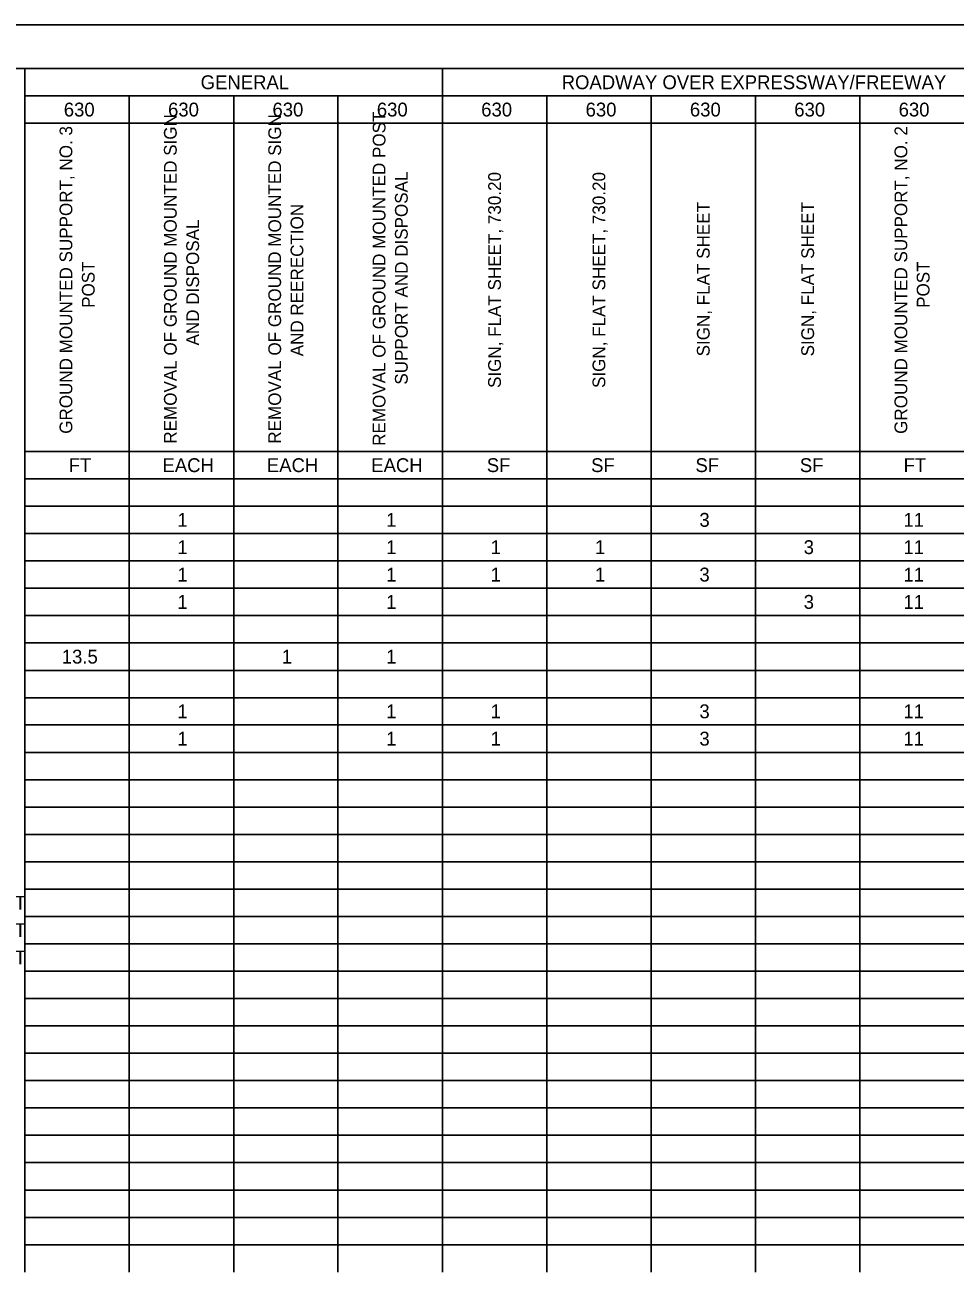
# Model space of a CAD drawing. Extents: x 0 to 34, y 0 to 22.
# Drawn here: x 12.87 to 23.52, y 7.71 to 22 of the extents above; entities that cross this region are included whole.
import ezdxf

# ---------------------------------------------------------------- set-up
doc = ezdxf.new("R2010")
doc.units = 0
for name, color, linetype in [('SH_Border', 7, 'Continuous'), ('SH_Cut_Line', 7, 'Continuous'), ('SH_Text', 7, 'Continuous')]:
    doc.layers.add(name, color=color, linetype=linetype)

msp = doc.modelspace()

# ---------------------------------------------------------------- linework, layer by layer
at = {"layer": 'SH_Border'}
msp.add_lwpolyline([(1.5, 21.5), (33.5, 21.5), (33.5, 0.5), (1.5, 0.5)], close=True, dxfattribs=at)
at = {"layer": 'SH_Cut_Line'}
msp.add_lwpolyline([(0, 0), (34, 0), (34, 22), (0, 22)], close=True, dxfattribs=at)
at = {"layer": 'SH_Text'}
for p, q in [((12.867, 21.5), (14.063, 21.5)), ((12.867, 21.5), (12.867, 21.187)), ((14.063, 21.5), (16.454, 21.5)), ((16.454, 21.5), (23.629, 21.5)), ((17.65, 21.5), (17.65, 21.187)), ((12.867, 21.187), (14.063, 21.187)), ((12.867, 21.187), (12.867, 20.873)), ((14.063, 21.187), (16.454, 21.187)), ((14.063, 21.187), (14.063, 20.873)), ((15.259, 21.187), (15.259, 20.873)), ((16.454, 21.187), (23.629, 21.187)), ((16.454, 21.187), (16.454, 20.873)), ((17.65, 21.187), (17.65, 20.873)), ((18.846, 21.187), (18.846, 20.873)), ((20.042, 21.187), (20.042, 20.873)), ((21.238, 21.187), (21.238, 20.873)), ((22.434, 21.187), (22.434, 20.873)), ((12.867, 20.873), (14.063, 20.873)), ((12.867, 20.873), (12.867, 20.56)), ((14.063, 20.873), (16.454, 20.873)), ((14.063, 20.873), (14.063, 20.56)), ((15.259, 20.873), (15.259, 20.56)), ((16.454, 20.873), (23.629, 20.873)), ((16.454, 20.873), (16.454, 20.56)), ((17.65, 20.873), (17.65, 20.56)), ((18.846, 20.873), (18.846, 20.56)), ((20.042, 20.873), (20.042, 20.56)), ((21.238, 20.873), (21.238, 20.56)), ((22.434, 20.873), (22.434, 20.56)), ((12.867, 20.56), (12.867, 19.933)), ((14.063, 20.56), (14.063, 19.933)), ((15.259, 20.56), (15.259, 19.933)), ((16.454, 20.56), (16.454, 19.933)), ((17.65, 20.56), (17.65, 19.933)), ((18.846, 20.56), (18.846, 19.933)), ((20.042, 20.56), (20.042, 19.933)), ((21.238, 20.56), (21.238, 19.933)), ((22.434, 20.56), (22.434, 19.933)), ((12.867, 19.933), (12.867, 19.619)), ((14.063, 19.933), (14.063, 19.619)), ((15.259, 19.933), (15.259, 19.619)), ((16.454, 19.933), (16.454, 19.619)), ((17.65, 19.933), (17.65, 19.619)), ((18.846, 19.933), (18.846, 19.619)), ((20.042, 19.933), (20.042, 19.619)), ((21.238, 19.933), (21.238, 19.619)), ((22.434, 19.933), (22.434, 19.619)), ((12.867, 19.619), (12.867, 19.306)), ((14.063, 19.619), (14.063, 19.306)), ((15.259, 19.619), (15.259, 19.306)), ((16.454, 19.619), (16.454, 19.306)), ((17.65, 19.619), (17.65, 19.306)), ((18.846, 19.619), (18.846, 19.306)), ((20.042, 19.619), (20.042, 19.306)), ((21.238, 19.619), (21.238, 19.306)), ((22.434, 19.619), (22.434, 19.306)), ((12.867, 19.306), (12.867, 18.993)), ((14.063, 19.306), (14.063, 18.993)), ((15.259, 19.306), (15.259, 18.993)), ((16.454, 19.306), (16.454, 18.993)), ((17.65, 19.306), (17.65, 18.993)), ((18.846, 19.306), (18.846, 18.993)), ((20.042, 19.306), (20.042, 18.993)), ((21.238, 19.306), (21.238, 18.993)), ((22.434, 19.306), (22.434, 18.993)), ((12.867, 18.993), (12.867, 18.679)), ((14.063, 18.993), (14.063, 18.679)), ((15.259, 18.993), (15.259, 18.679)), ((16.454, 18.993), (16.454, 18.679)), ((17.65, 18.993), (17.65, 18.679)), ((18.846, 18.993), (18.846, 18.679)), ((20.042, 18.993), (20.042, 18.679)), ((21.238, 18.993), (21.238, 18.679)), ((22.434, 18.993), (22.434, 18.679)), ((12.867, 18.679), (12.867, 18.366)), ((14.063, 18.679), (14.063, 18.366)), ((15.259, 18.679), (15.259, 18.366)), ((16.454, 18.679), (16.454, 18.366)), ((17.65, 18.679), (17.65, 18.366)), ((18.846, 18.679), (18.846, 18.366)), ((20.042, 18.679), (20.042, 18.366)), ((21.238, 18.679), (21.238, 18.366)), ((22.434, 18.679), (22.434, 18.366)), ((12.867, 18.366), (12.867, 18.052)), ((14.063, 18.366), (14.063, 18.052)), ((15.259, 18.366), (15.259, 18.052)), ((16.454, 18.366), (16.454, 18.052)), ((17.65, 18.366), (17.65, 18.052)), ((18.846, 18.366), (18.846, 18.052)), ((20.042, 18.366), (20.042, 18.052)), ((21.238, 18.366), (21.238, 18.052)), ((22.434, 18.366), (22.434, 18.052)), ((12.867, 18.052), (12.867, 17.739)), ((14.063, 18.052), (14.063, 17.739)), ((15.259, 18.052), (15.259, 17.739)), ((16.454, 18.052), (16.454, 17.739)), ((17.65, 18.052), (17.65, 17.739)), ((18.846, 18.052), (18.846, 17.739)), ((20.042, 18.052), (20.042, 17.739)), ((21.238, 18.052), (21.238, 17.739)), ((22.434, 18.052), (22.434, 17.739)), ((12.867, 17.739), (12.867, 17.425)), ((14.063, 17.739), (14.063, 17.425)), ((15.259, 17.739), (15.259, 17.425)), ((16.454, 17.739), (16.454, 17.425)), ((17.65, 17.739), (17.65, 17.425)), ((18.846, 17.739), (18.846, 17.425)), ((20.042, 17.739), (20.042, 17.425)), ((21.238, 17.739), (21.238, 17.425)), ((22.434, 17.739), (22.434, 17.425)), ((12.867, 17.425), (12.867, 16.799)), ((14.063, 17.425), (14.063, 16.799)), ((15.259, 17.425), (15.259, 16.799)), ((16.454, 17.425), (16.454, 16.799)), ((17.65, 17.425), (17.65, 16.799)), ((18.846, 17.425), (18.846, 16.799)), ((20.042, 17.425), (20.042, 16.799)), ((21.238, 17.425), (21.238, 16.799)), ((22.434, 17.425), (22.434, 16.799)), ((12.867, 17.112), (14.063, 17.112)), ((14.063, 17.112), (16.454, 17.112)), ((16.454, 17.112), (23.629, 17.112)), ((12.867, 16.799), (14.063, 16.799)), ((12.867, 16.799), (12.867, 16.485)), ((14.063, 16.799), (16.454, 16.799)), ((14.063, 16.799), (14.063, 16.485)), ((15.259, 16.799), (15.259, 16.485)), ((16.454, 16.799), (23.629, 16.799)), ((16.454, 16.799), (16.454, 16.485)), ((17.65, 16.799), (17.65, 16.485)), ((18.846, 16.799), (18.846, 16.485)), ((20.042, 16.799), (20.042, 16.485)), ((21.238, 16.799), (21.238, 16.485)), ((22.434, 16.799), (22.434, 16.485)), ((12.867, 16.485), (14.063, 16.485)), ((12.867, 16.485), (12.867, 15.231)), ((14.063, 16.485), (16.454, 16.485)), ((14.063, 16.485), (14.063, 15.231)), ((15.259, 16.485), (15.259, 15.231)), ((16.454, 16.485), (23.629, 16.485)), ((16.454, 16.485), (16.454, 15.231)), ((17.65, 16.485), (17.65, 15.231)), ((18.846, 16.485), (18.846, 15.231)), ((20.042, 16.485), (20.042, 15.231)), ((21.238, 16.485), (21.238, 15.231)), ((22.434, 16.485), (22.434, 15.231)), ((12.867, 16.172), (14.063, 16.172)), ((14.063, 16.172), (16.454, 16.172)), ((16.454, 16.172), (23.629, 16.172)), ((12.867, 15.858), (14.063, 15.858)), ((14.063, 15.858), (16.454, 15.858)), ((16.454, 15.858), (23.629, 15.858)), ((12.867, 15.545), (14.063, 15.545)), ((14.063, 15.545), (16.454, 15.545)), ((16.454, 15.545), (23.629, 15.545)), ((12.867, 15.231), (14.063, 15.231)), ((12.867, 15.231), (12.867, 14.291)), ((14.063, 15.231), (16.454, 15.231)), ((14.063, 15.231), (14.063, 14.291)), ((15.259, 15.231), (15.259, 14.291)), ((16.454, 15.231), (23.629, 15.231)), ((16.454, 15.231), (16.454, 14.291)), ((17.65, 15.231), (17.65, 14.291)), ((18.846, 15.231), (18.846, 14.291)), ((20.042, 15.231), (20.042, 14.291)), ((21.238, 15.231), (21.238, 14.291)), ((22.434, 15.231), (22.434, 14.291)), ((12.867, 14.918), (14.063, 14.918)), ((14.063, 14.918), (16.454, 14.918)), ((16.454, 14.918), (23.629, 14.918)), ((12.867, 14.604), (14.063, 14.604)), ((14.063, 14.604), (16.454, 14.604)), ((16.454, 14.604), (23.629, 14.604)), ((12.867, 14.291), (14.063, 14.291)), ((12.867, 14.291), (12.867, 13.664)), ((14.063, 14.291), (16.454, 14.291)), ((14.063, 14.291), (14.063, 13.664)), ((15.259, 14.291), (15.259, 13.664)), ((16.454, 14.291), (23.629, 14.291)), ((16.454, 14.291), (16.454, 13.664)), ((17.65, 14.291), (17.65, 13.664)), ((18.846, 14.291), (18.846, 13.664)), ((20.042, 14.291), (20.042, 13.664)), ((21.238, 14.291), (21.238, 13.664)), ((22.434, 14.291), (22.434, 13.664)), ((12.867, 13.978), (14.063, 13.978)), ((14.063, 13.978), (16.454, 13.978)), ((16.454, 13.978), (23.629, 13.978)), ((12.867, 13.664), (14.063, 13.664)), ((12.867, 13.664), (12.867, 13.351)), ((14.063, 13.664), (16.454, 13.664)), ((14.063, 13.664), (14.063, 13.351)), ((15.259, 13.664), (15.259, 13.351)), ((16.454, 13.664), (23.629, 13.664)), ((16.454, 13.664), (16.454, 13.351)), ((17.65, 13.664), (17.65, 13.351)), ((18.846, 13.664), (18.846, 13.351)), ((20.042, 13.664), (20.042, 13.351)), ((21.238, 13.664), (21.238, 13.351)), ((22.434, 13.664), (22.434, 13.351)), ((12.867, 13.351), (14.063, 13.351)), ((12.867, 13.351), (12.867, 13.037)), ((14.063, 13.351), (16.454, 13.351)), ((14.063, 13.351), (14.063, 13.037)), ((15.259, 13.351), (15.259, 13.037)), ((16.454, 13.351), (23.629, 13.351)), ((16.454, 13.351), (16.454, 13.037)), ((17.65, 13.351), (17.65, 13.037)), ((18.846, 13.351), (18.846, 13.037)), ((20.042, 13.351), (20.042, 13.037)), ((21.238, 13.351), (21.238, 13.037)), ((22.434, 13.351), (22.434, 13.037)), ((12.867, 13.037), (14.063, 13.037)), ((12.867, 13.037), (12.867, 12.41)), ((14.063, 13.037), (16.454, 13.037)), ((14.063, 13.037), (14.063, 12.41)), ((15.259, 13.037), (15.259, 12.41)), ((16.454, 13.037), (23.629, 13.037)), ((16.454, 13.037), (16.454, 12.41)), ((17.65, 13.037), (17.65, 12.41)), ((18.846, 13.037), (18.846, 12.41)), ((20.042, 13.037), (20.042, 12.41)), ((21.238, 13.037), (21.238, 12.41)), ((22.434, 13.037), (22.434, 12.41)), ((12.867, 12.724), (14.063, 12.724)), ((14.063, 12.724), (16.454, 12.724)), ((16.454, 12.724), (23.629, 12.724)), ((12.867, 12.41), (14.063, 12.41)), ((12.867, 12.41), (12.867, 11.47)), ((14.063, 12.41), (16.454, 12.41)), ((14.063, 12.41), (14.063, 11.47)), ((15.259, 12.41), (15.259, 11.47)), ((16.454, 12.41), (23.629, 12.41)), ((16.454, 12.41), (16.454, 11.47)), ((17.65, 12.41), (17.65, 11.47)), ((18.846, 12.41), (18.846, 11.47)), ((20.042, 12.41), (20.042, 11.47)), ((21.238, 12.41), (21.238, 11.47)), ((22.434, 12.41), (22.434, 11.47)), ((12.867, 12.097), (14.063, 12.097)), ((14.063, 12.097), (16.454, 12.097)), ((16.454, 12.097), (23.629, 12.097)), ((12.867, 11.784), (14.063, 11.784)), ((14.063, 11.784), (16.454, 11.784)), ((16.454, 11.784), (23.629, 11.784)), ((12.867, 11.47), (14.063, 11.47)), ((12.867, 11.47), (12.867, 10.843)), ((14.063, 11.47), (16.454, 11.47)), ((14.063, 11.47), (14.063, 10.843)), ((15.259, 11.47), (15.259, 10.843)), ((16.454, 11.47), (23.629, 11.47)), ((16.454, 11.47), (16.454, 10.843)), ((17.65, 11.47), (17.65, 10.843)), ((18.846, 11.47), (18.846, 10.843)), ((20.042, 11.47), (20.042, 10.843)), ((21.238, 11.47), (21.238, 10.843)), ((22.434, 11.47), (22.434, 10.843)), ((12.867, 11.157), (14.063, 11.157)), ((14.063, 11.157), (16.454, 11.157)), ((16.454, 11.157), (23.629, 11.157)), ((12.867, 10.843), (14.063, 10.843)), ((12.867, 10.843), (12.867, 9.903)), ((14.063, 10.843), (16.454, 10.843)), ((14.063, 10.843), (14.063, 9.903)), ((15.259, 10.843), (15.259, 9.903)), ((16.454, 10.843), (23.629, 10.843)), ((16.454, 10.843), (16.454, 9.903)), ((17.65, 10.843), (17.65, 9.903)), ((18.846, 10.843), (18.846, 9.903)), ((20.042, 10.843), (20.042, 9.903)), ((21.238, 10.843), (21.238, 9.903)), ((22.434, 10.843), (22.434, 9.903)), ((12.867, 10.53), (14.063, 10.53)), ((14.063, 10.53), (16.454, 10.53)), ((16.454, 10.53), (23.629, 10.53)), ((12.867, 10.216), (14.063, 10.216)), ((14.063, 10.216), (16.454, 10.216)), ((16.454, 10.216), (23.629, 10.216)), ((12.867, 9.903), (14.063, 9.903)), ((12.867, 9.903), (12.867, 9.276)), ((14.063, 9.903), (16.454, 9.903)), ((14.063, 9.903), (14.063, 9.276)), ((15.259, 9.903), (15.259, 9.276)), ((16.454, 9.903), (23.629, 9.903)), ((16.454, 9.903), (16.454, 9.276)), ((17.65, 9.903), (17.65, 9.276)), ((18.846, 9.903), (18.846, 9.276)), ((20.042, 9.903), (20.042, 9.276)), ((21.238, 9.903), (21.238, 9.276)), ((22.434, 9.903), (22.434, 9.276)), ((12.867, 9.59), (14.063, 9.59)), ((14.063, 9.59), (16.454, 9.59)), ((16.454, 9.59), (23.629, 9.59)), ((12.867, 9.276), (14.063, 9.276)), ((12.867, 9.276), (12.867, 8.336)), ((14.063, 9.276), (16.454, 9.276)), ((14.063, 9.276), (14.063, 8.336)), ((15.259, 9.276), (15.259, 8.336)), ((16.454, 9.276), (23.629, 9.276)), ((16.454, 9.276), (16.454, 8.336)), ((17.65, 9.276), (17.65, 8.336)), ((18.846, 9.276), (18.846, 8.336)), ((20.042, 9.276), (20.042, 8.336)), ((21.238, 9.276), (21.238, 8.336)), ((22.434, 9.276), (22.434, 8.336)), ((12.867, 8.963), (14.063, 8.963)), ((14.063, 8.963), (16.454, 8.963)), ((16.454, 8.963), (23.629, 8.963)), ((12.867, 8.649), (14.063, 8.649)), ((14.063, 8.649), (16.454, 8.649)), ((16.454, 8.649), (23.629, 8.649)), ((12.867, 8.336), (14.063, 8.336)), ((12.867, 8.336), (12.867, 7.709)), ((14.063, 8.336), (16.454, 8.336)), ((14.063, 8.336), (14.063, 7.709)), ((15.259, 8.336), (15.259, 7.709)), ((16.454, 8.336), (23.629, 8.336)), ((16.454, 8.336), (16.454, 7.709)), ((17.65, 8.336), (17.65, 7.709)), ((18.846, 8.336), (18.846, 7.709)), ((20.042, 8.336), (20.042, 7.709)), ((21.238, 8.336), (21.238, 7.709)), ((22.434, 8.336), (22.434, 7.709)), ((12.867, 8.022), (14.063, 8.022)), ((14.063, 8.022), (16.454, 8.022)), ((16.454, 8.022), (23.629, 8.022))]:
    msp.add_line(p, q, dxfattribs=at)

# ---------------------------------------------------------------- texts
for s, height, p in [('GENERAL', 0.1586, (14.88, 21.264)), ('ROADWAY OVER EXPRESSWAY/FREEWAY', 0.15858, (19.017, 21.264)), ('630', 0.1586, (13.312, 20.951)), ('630', 0.1586, (14.507, 20.951)), ('630', 0.1586, (15.703, 20.951)), ('630', 0.1586, (16.899, 20.951)), ('630', 0.1586, (18.095, 20.951)), ('630', 0.1586, (19.291, 20.951)), ('630', 0.1586, (20.486, 20.951)), ('630', 0.1586, (21.682, 20.951)), ('630', 0.1586, (22.878, 20.951)), ('FT', 0.1586, (13.368, 16.876)), ('EACH', 0.1586, (14.443, 16.876)), ('EACH', 0.1586, (15.639, 16.876)), ('EACH', 0.1586, (16.835, 16.876)), ('SF', 0.1586, (18.159, 16.876)), ('SF', 0.1586, (19.354, 16.876)), ('SF', 0.1586, (20.55, 16.876)), ('SF', 0.1586, (21.746, 16.876)), ('FT', 0.1586, (22.935, 16.876)), ('1', 0.159, (14.614, 16.249)), ('1', 0.159, (17.006, 16.249)), ('3', 0.159, (20.595, 16.249)), ('11', 0.1586, (22.933, 16.249)), ('1', 0.159, (14.614, 15.936)), ('1', 0.159, (17.006, 15.936)), ('1', 0.159, (18.202, 15.936)), ('1', 0.159, (19.398, 15.936)), ('3', 0.159, (21.79, 15.936)), ('11', 0.1586, (22.933, 15.936)), ('1', 0.159, (14.614, 15.622)), ('1', 0.159, (17.006, 15.622)), ('1', 0.159, (18.202, 15.622)), ('1', 0.159, (19.398, 15.622)), ('3', 0.159, (20.595, 15.622)), ('11', 0.1586, (22.933, 15.622)), ('1', 0.159, (14.614, 15.309)), ('1', 0.159, (17.006, 15.309)), ('3', 0.159, (21.79, 15.309)), ('11', 0.1586, (22.933, 15.309)), ('13.5', 0.1586, (13.289, 14.682)), ('1', 0.159, (15.81, 14.682)), ('1', 0.159, (17.006, 14.682)), ('1', 0.159, (14.614, 14.055)), ('1', 0.159, (17.006, 14.055)), ('1', 0.159, (18.202, 14.055)), ('3', 0.159, (20.595, 14.055)), ('11', 0.1586, (22.933, 14.055)), ('1', 0.159, (14.614, 13.742)), ('1', 0.159, (17.006, 13.742)), ('1', 0.159, (18.202, 13.742)), ('3', 0.159, (20.595, 13.742)), ('11', 0.1586, (22.933, 13.742)), ('RT/LT', 0.1586, (12.29, 11.861)), ('RT/LT', 0.1586, (12.29, 11.548)), ('RT/LT', 0.1586, (12.29, 11.234))]:
    msp.add_text(s, height=height, dxfattribs=at).set_placement(p)
for s, height, p in [('REMOVAL OF GROUND MOUNTED SIGN ', 0.14604, (14.606, 17.202)), ('REMOVAL OF GROUND MOUNTED SIGN ', 0.14604, (15.802, 17.202)), ('REMOVAL OF GROUND MOUNTED POST ', 0.14604, (16.998, 17.177)), ('GROUND MOUNTED SUPPORT, NO. 3 ', 0.14604, (13.41, 17.315)), ('GROUND MOUNTED SUPPORT, NO. 2 ', 0.14604, (22.977, 17.314)), ('SUPPORT AND DISPOSAL', 0.14604, (17.253, 17.878)), ('SIGN, FLAT SHEET, 730.20', 0.14604, (18.321, 17.84)), ('SIGN, FLAT SHEET, 730.20', 0.14604, (19.517, 17.84)), ('AND REERECTION', 0.14604, (16.057, 18.203)), ('SIGN, FLAT SHEET', 0.14604, (20.713, 18.202)), ('SIGN, FLAT SHEET', 0.14604, (21.909, 18.202)), ('AND DISPOSAL', 0.14604, (14.862, 18.327)), ('POST', 0.146, (13.666, 18.758)), ('POST', 0.146, (23.232, 18.758))]:
    msp.add_text(s, height=height, rotation=90, dxfattribs=at).set_placement(p)

doc.saveas('drawing.dxf')
